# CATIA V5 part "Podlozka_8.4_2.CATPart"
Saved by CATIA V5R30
Part number: Podlozka_8.4_2
Definition: DIN 6340-8.4_1
Nomenclature: DIN 6340-8.4_1
Source: Unknown
Description: PART--DESC
Bounding box of the stored display mesh (mm): x 120.5 to 138.5, y -27.5 to -9.5, z 83.7 to 86.2
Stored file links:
  E:\Bakalarka\Model\Forma_v7\Podlozka_8.4_2.CATPart
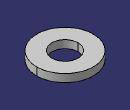
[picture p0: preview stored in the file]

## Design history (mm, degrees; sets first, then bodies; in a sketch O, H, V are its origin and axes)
Body1 "MANIFOLD_SOLID_BREP #3658" (main body)
  Solid1: solid without history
